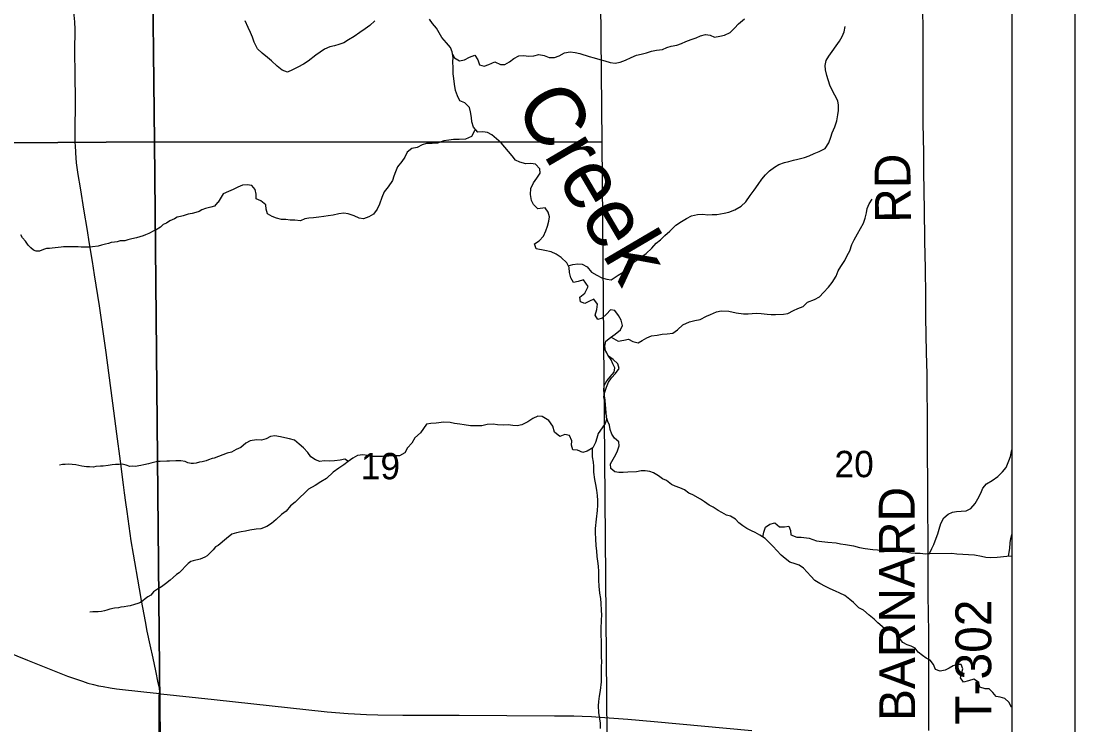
# Model space of a CAD drawing. Extents: x 0 to 34, y 0 to 22.
# Drawn here: x 23.087 to 24.758, y 10.698 to 11.815 of the extents above; entities that cross this region are included whole.
import ezdxf

# ---------------------------------------------------------------- set-up
doc = ezdxf.new("R2010")
doc.units = 0
for name, color, linetype in [('GM_X_County_Road', 7, 'Continuous'), ('GM_X_Minor_River', 7, 'Continuous'), ('GM_X_Minor_River_Text', 7, 'Continuous'), ('GM_X_Section', 7, 'Continuous'), ('GM_X_Section_Text', 7, 'Continuous'), ('GM_X_Township_Road', 7, 'Continuous'), ('GM_X_Township_Road_Text', 7, 'Continuous'), ('GM_X_US_Route', 7, 'Continuous'), ('SH_Data', 7, 'Continuous')]:
    doc.layers.add(name, color=color, linetype=linetype)

msp = doc.modelspace()

# ---------------------------------------------------------------- linework, layer by layer
at = {"layer": 'GM_X_County_Road'}
for points in [[(23.1726, 11.6218), (23.1725, 11.6372), (23.1727, 11.69), (23.1722, 11.7304), (23.1721, 11.7677), (23.1722, 11.8019), (23.1717, 11.8143), (23.1704, 11.8297), (23.1681, 11.8482), (23.1633, 11.8789), (23.1585, 11.9065), (23.1536, 11.934), (23.1493, 11.9553), (23.1329, 12.0344), (23.1224, 12.0831), (23.1147, 12.1196), (23.1137, 12.124)], [(23.3062, 10.7482), (23.3065, 10.7526), (23.3062, 10.7553), (23.3061, 10.7566), (23.3042, 10.7651), (23.3004, 10.7844), (23.2959, 10.8046), (23.2912, 10.8258), (23.2868, 10.8471), (23.2839, 10.8624), (23.2778, 10.896), (23.2745, 10.9144), (23.2717, 10.9296), (23.2668, 10.9571), (23.2647, 10.9693), (23.2614, 10.9908), (23.255, 11.0369), (23.253, 11.0512), (23.2508, 11.067), (23.2492, 11.0795), (23.2443, 11.117), (23.2385, 11.1601), (23.2338, 11.1971), (23.2218, 11.2896), (23.2109, 11.3634), (23.2033, 11.4125), (23.1997, 11.434), (23.1951, 11.4616), (23.1912, 11.4861), (23.1868, 11.5137), (23.1808, 11.5505), (23.1773, 11.572), (23.1747, 11.5905), (23.1733, 11.606), (23.1727, 11.6185), (23.1726, 11.6218)], [(23.3087, 10.1096), (23.3086, 10.1172), (23.3085, 10.1512), (23.3083, 10.2038), (23.3081, 10.2441), (23.3078, 10.3093), (23.3076, 10.3744), (23.3074, 10.4208), (23.3069, 10.4645), (23.3064, 10.5577), (23.3061, 10.6228), (23.3057, 10.6663), (23.3054, 10.6973), (23.3054, 10.7344), (23.3054, 10.7399), (23.3056, 10.7424), (23.3058, 10.7444), (23.3062, 10.7482)]]:
    msp.add_lwpolyline(points, dxfattribs=at)
at = {"layer": 'GM_X_Minor_River'}
for points in [[(23.7541, 11.7894), (23.7494, 11.7966), (23.7456, 11.8041), (23.7391, 11.8113), (23.7344, 11.8185)], [(23.7709, 11.7626), (23.7741, 11.7568), (23.7818, 11.7523), (23.7897, 11.7539), (23.7977, 11.7578), (23.806, 11.7609), (23.811, 11.7537), (23.8134, 11.7457), (23.821, 11.7439), (23.8282, 11.7463), (23.8377, 11.7505), (23.8468, 11.7464), (23.8537, 11.7461), (23.8612, 11.7507), (23.868, 11.7557), (23.876, 11.7603), (23.884, 11.7604), (23.8916, 11.7597), (23.8999, 11.7601), (23.9075, 11.7621), (23.9163, 11.7607), (23.9243, 11.7573), (23.9327, 11.7574), (23.9399, 11.7601), (23.9486, 11.7647), (23.9573, 11.7663), (23.9653, 11.7656), (23.9725, 11.7638), (23.9874, 11.759), (23.9954, 11.7567), (24.0046, 11.7545), (24.0126, 11.7523), (24.0209, 11.7497), (24.0289, 11.7487), (24.0369, 11.7502), (24.0453, 11.7534), (24.054, 11.7576), (24.0627, 11.7611), (24.0699, 11.7627), (24.0786, 11.765), (24.0866, 11.7674), (24.0942, 11.769), (24.1037, 11.7702), (24.1105, 11.7733), (24.1177, 11.7752), (24.1268, 11.7768), (24.134, 11.7796), (24.1408, 11.783), (24.1495, 11.7861), (24.1571, 11.7885), (24.1643, 11.7916), (24.1719, 11.7939), (24.1795, 11.7929), (24.1864, 11.7899), (24.1947, 11.7911), (24.202, 11.7927), (24.211, 11.7973), (24.2178, 11.8038), (24.2246, 11.8111), (24.2337, 11.8188)], [(23.6478, 11.8159), (23.6398, 11.8082), (23.6323, 11.8028), (23.624, 11.7971), (23.6149, 11.7909), (23.6058, 11.7855), (23.5986, 11.7809), (23.5907, 11.7782), (23.5838, 11.7762), (23.5763, 11.7742), (23.5679, 11.7707), (23.5611, 11.7661), (23.5539, 11.7611), (23.5418, 11.7519), (23.5343, 11.7469), (23.5256, 11.7423), (23.5173, 11.738), (23.5093, 11.7341), (23.5009, 11.7375), (23.4929, 11.7439), (23.484, 11.7522), (23.4772, 11.7574), (23.4691, 11.7642), (23.4618, 11.7714), (23.4564, 11.782), (23.4537, 11.7896), (23.4506, 11.7972), (23.4467, 11.8051), (23.4421, 11.8157)], [(23.9545, 11.4271), (23.9617, 11.4291), (23.9697, 11.4303), (23.9765, 11.4296), (23.9845, 11.4251), (23.9915, 11.4171), (23.9995, 11.4119), (24.0079, 11.4081), (24.0155, 11.4056), (24.0227, 11.4045), (24.0337, 11.4122), (24.0413, 11.4168), (24.0492, 11.4237), (24.0582, 11.4329), (24.0658, 11.4379), (24.0779, 11.4467), (24.0869, 11.4552), (24.0937, 11.4629), (24.1005, 11.4682), (24.1077, 11.4748), (24.1156, 11.482), (24.125, 11.4912), (24.1341, 11.497), (24.1417, 11.502), (24.15, 11.5063), (24.1591, 11.5083), (24.1679, 11.5087), (24.1755, 11.508), (24.1827, 11.5081), (24.1899, 11.5085), (24.2017, 11.5105), (24.2093, 11.5121), (24.2188, 11.5156), (24.2286, 11.5218), (24.2361, 11.5283), (24.2429, 11.5386), (24.2493, 11.547), (24.2557, 11.5558), (24.2613, 11.5642), (24.267, 11.5711), (24.2737, 11.5776), (24.2817, 11.5834), (24.2885, 11.5876), (24.2972, 11.5911), (24.3044, 11.5923), (24.3116, 11.5947), (24.3184, 11.5963), (24.3291, 11.599), (24.3363, 11.6017), (24.3442, 11.6052), (24.3522, 11.6083), (24.3617, 11.6133), (24.3677, 11.6221), (24.371, 11.6309), (24.3728, 11.6378), (24.3769, 11.6473), (24.3803, 11.6568), (24.3821, 11.6667), (24.3832, 11.6736), (24.3831, 11.6816), (24.3819, 11.6888), (24.3773, 11.6975), (24.3696, 11.7119), (24.3668, 11.7218), (24.3645, 11.729), (24.3625, 11.7377), (24.3617, 11.7449), (24.3635, 11.7525), (24.3676, 11.7594), (24.3729, 11.7671), (24.3793, 11.7759), (24.3845, 11.7835), (24.3887, 11.7908), (24.392, 11.7984), (24.3935, 11.8064)], [(24.0155, 11.188), (24.0135, 11.1949), (24.0127, 11.2025), (24.0122, 11.2105), (24.0106, 11.2188), (24.0125, 11.2264), (24.0151, 11.2344), (24.018, 11.2424), (24.0229, 11.2493), (24.0293, 11.2562), (24.035, 11.2639), (24.033, 11.2715), (24.0257, 11.2782), (24.0184, 11.2835), (24.0134, 11.2922), (24.0126, 11.2994), (24.0141, 11.3074), (24.0212, 11.3132), (24.0288, 11.3186), (24.0371, 11.3251), (24.0405, 11.332), (24.0381, 11.3407), (24.0342, 11.3483), (24.0285, 11.3558), (24.0216, 11.3573), (24.0148, 11.35), (24.008, 11.3439), (24.0012, 11.3415), (23.997, 11.3487), (23.9996, 11.3575), (24.0006, 11.3659), (23.9949, 11.3738), (23.988, 11.3707), (23.9805, 11.3672), (23.9736, 11.3698), (23.9728, 11.3771), (23.9807, 11.3836), (23.9859, 11.3943), (23.9786, 11.4049), (23.9703, 11.4021), (23.9627, 11.4002), (23.9585, 11.4077), (23.9561, 11.4161), (23.956, 11.4241), (23.9522, 11.4316), (23.943, 11.4399), (23.9353, 11.4452), (23.9273, 11.4489), (23.9174, 11.4515), (23.9037, 11.4537), (23.9006, 11.462), (23.9085, 11.4667), (23.9149, 11.4739), (23.919, 11.4827), (23.9213, 11.4896), (23.9235, 11.4976), (23.9246, 11.5048), (23.9226, 11.512), (23.9176, 11.5188), (23.9062, 11.5176), (23.8993, 11.524), (23.8962, 11.5308), (23.8946, 11.5403), (23.8953, 11.5498), (23.8994, 11.5586), (23.9043, 11.5662), (23.9099, 11.5739), (23.9095, 11.5807), (23.9022, 11.5883), (23.8953, 11.5894), (23.8873, 11.5885), (23.8778, 11.5915), (23.8706, 11.5945), (23.8652, 11.6013), (23.8594, 11.6081), (23.854, 11.6153), (23.8479, 11.6221), (23.8406, 11.6285), (23.833, 11.6345), (23.8261, 11.6386), (23.8188, 11.6393), (23.8112, 11.6389), (23.8043, 11.6468), (23.8016, 11.6552), (23.8008, 11.6624), (23.7996, 11.6711), (23.7976, 11.6783), (23.7903, 11.6855), (23.7823, 11.6885), (23.7788, 11.6968), (23.7757, 11.7051), (23.7741, 11.7154), (23.7729, 11.7241), (23.7717, 11.7317), (23.772, 11.7412), (23.7715, 11.7504), (23.7718, 11.7576), (23.7702, 11.7663), (23.7675, 11.7731), (23.7614, 11.7807), (23.7541, 11.7894)], [(23.8077, 11.643), (23.8055, 11.6411), (23.801, 11.6323), (23.7912, 11.6277), (23.7813, 11.6272), (23.7722, 11.6272), (23.765, 11.6263), (23.757, 11.6251), (23.7471, 11.6216), (23.7388, 11.6208), (23.7297, 11.6211), (23.7228, 11.6188), (23.7149, 11.6149), (23.7061, 11.6129), (23.699, 11.6072), (23.6952, 11.5991), (23.6904, 11.5923), (23.6836, 11.5838), (23.6806, 11.5762), (23.6776, 11.5693), (23.6754, 11.5625), (23.669, 11.5525), (23.6626, 11.5441), (23.6585, 11.5353), (23.6548, 11.525), (23.6511, 11.5166), (23.6454, 11.509), (23.6382, 11.5048), (23.6295, 11.5016), (23.6227, 11.5027), (23.6147, 11.5065), (23.6051, 11.5094), (23.5983, 11.5105), (23.5903, 11.5093), (23.5816, 11.5073), (23.5736, 11.5065), (23.5668, 11.5053), (23.5588, 11.5041), (23.5504, 11.5029), (23.5432, 11.5025), (23.5364, 11.5016), (23.5296, 11.4985), (23.5208, 11.4992), (23.5132, 11.4995), (23.5063, 11.5003), (23.4995, 11.5006), (23.4919, 11.5024), (23.4846, 11.505), (23.4774, 11.5095), (23.4754, 11.5167), (23.4746, 11.5239), (23.4669, 11.53), (23.4597, 11.5333), (23.4592, 11.5406), (23.458, 11.5478), (23.4527, 11.5546), (23.445, 11.5556), (23.4378, 11.5548), (23.4306, 11.5517), (23.423, 11.5479), (23.4155, 11.5451), (23.4071, 11.5409), (23.3991, 11.5281)], [(24.0223, 11.3139), (24.0338, 11.3072), (24.0426, 11.3092), (24.0498, 11.3104), (24.057, 11.3066), (24.065, 11.3048), (24.0718, 11.3087), (24.079, 11.3129), (24.0862, 11.3156), (24.0953, 11.3168), (24.1033, 11.3184), (24.1113, 11.3189), (24.12, 11.3201), (24.1276, 11.3255), (24.1359, 11.3331), (24.1469, 11.3378), (24.1552, 11.3401), (24.1636, 11.3417), (24.1734, 11.3468), (24.1802, 11.3495), (24.1893, 11.3541), (24.1969, 11.3557), (24.2091, 11.355), (24.2205, 11.3525), (24.2323, 11.3507), (24.2395, 11.3507), (24.2525, 11.3516), (24.2601, 11.3513), (24.2696, 11.3502), (24.2764, 11.3499), (24.2833, 11.3496), (24.2958, 11.3504), (24.3027, 11.3512), (24.3114, 11.3563), (24.3186, 11.3594), (24.3269, 11.3625), (24.3337, 11.369), (24.3451, 11.3736), (24.353, 11.3775), (24.359, 11.3844), (24.3669, 11.3928), (24.373, 11.4005), (24.3793, 11.4104), (24.3823, 11.4188), (24.3868, 11.4261), (24.3932, 11.4353), (24.3966, 11.4433), (24.401, 11.4509), (24.404, 11.4608), (24.4077, 11.4681), (24.413, 11.4776), (24.4179, 11.4864), (24.4224, 11.4944), (24.4253, 11.5024), (24.4272, 11.5108), (24.4282, 11.5181), (24.4316, 11.5253), (24.4365, 11.5326)], [(23.3991, 11.5281), (23.3983, 11.5273), (23.3935, 11.5215), (23.3874, 11.5199), (23.3791, 11.5179), (23.3734, 11.5156), (23.3689, 11.5129), (23.3635, 11.5116), (23.3579, 11.51), (23.3514, 11.5088), (23.3438, 11.5064), (23.3393, 11.5052), (23.334, 11.504), (23.3298, 11.5013), (23.3226, 11.4982), (23.317, 11.4947), (23.3117, 11.4927), (23.3079, 11.4885), (23.3008, 11.4842), (23.297, 11.4826), (23.2891, 11.478), (23.2841, 11.476), (23.2804, 11.4744), (23.2698, 11.4713), (23.2622, 11.47), (23.2561, 11.468), (23.2512, 11.4668), (23.2436, 11.4664), (23.239, 11.4652), (23.2349, 11.4643), (23.2295, 11.4639), (23.225, 11.4623), (23.2204, 11.4611), (23.2144, 11.4599), (23.2091, 11.4583), (23.2, 11.457), (23.1962, 11.4566), (23.1817, 11.4564), (23.1771, 11.4571), (23.1539, 11.4568), (23.1501, 11.4564), (23.1407, 11.4555), (23.1361, 11.4551), (23.1315, 11.4542), (23.127, 11.4542), (23.122, 11.453), (23.116, 11.4502), (23.1107, 11.4502), (23.1065, 11.4516), (23.1022, 11.4554), (23.0976, 11.4599), (23.0937, 11.4663), (23.0887, 11.4711), (23.0864, 11.476)], [(24.4559, 10.8514), (24.4456, 10.8607), (24.4395, 10.8664), (24.4314, 10.8724), (24.4226, 10.8807), (24.4154, 10.8844), (24.4069, 10.8927), (24.4008, 10.8976), (24.3932, 10.904), (24.3851, 10.9078), (24.3783, 10.9108), (24.3699, 10.9145), (24.3626, 10.9182), (24.3534, 10.9227), (24.3454, 10.9276), (24.3389, 10.9344), (24.3274, 10.9472), (24.3205, 10.9521), (24.314, 10.954), (24.306, 10.9566), (24.2984, 10.9626), (24.2922, 10.9679), (24.2853, 10.9754), (24.2796, 10.9814), (24.2727, 10.9886), (24.2665, 10.9943), (24.2581, 10.9995), (24.2509, 11.0036), (24.2448, 11.0063), (24.2375, 11.01), (24.231, 11.0145), (24.2249, 11.019), (24.2195, 11.0251), (24.2119, 11.0296), (24.2054, 11.0314), (24.1981, 11.0355), (24.192, 11.0389), (24.1844, 11.0442), (24.1779, 11.0472), (24.1702, 11.0524), (24.1641, 11.0565), (24.1519, 11.0633), (24.1458, 11.0663), (24.1385, 11.0715), (24.1312, 11.0749), (24.124, 11.0771), (24.1179, 11.0801), (24.1102, 11.0865), (24.1041, 11.0891), (24.0976, 11.0936), (24.0896, 11.0985), (24.0835, 11.1004), (24.0763, 11.1018), (24.0698, 11.1018), (24.0626, 11.1002), (24.0489, 11.0993), (24.0417, 11.0989), (24.0348, 11.0988), (24.0284, 11.1003), (24.0219, 11.1056), (24.0214, 11.1128), (24.0255, 11.1201), (24.03, 11.1273), (24.0327, 11.1334), (24.0352, 11.1411), (24.0344, 11.1475), (24.0275, 11.1535), (24.0233, 11.16), (24.0206, 11.1672), (24.0198, 11.174), (24.017, 11.1801), (24.0151, 11.1861), (24.0143, 11.1941), (24.0134, 11.2063), (24.013, 11.2139), (24.0121, 11.2207), (24.0109, 11.2295), (24.0112, 11.2371), (24.0157, 11.2447), (24.021, 11.2508), (24.027, 11.2581), (24.0281, 11.265), (24.025, 11.2714), (24.0227, 11.2775), (24.0177, 11.2846), (24.0142, 11.2915), (24.0107, 11.2975), (24.0108, 11.2996)], [(24.0156, 11.1847), (24.0129, 11.177), (24.008, 11.1701), (24.0016, 11.1609), (23.9998, 11.1537), (23.9976, 11.1464), (23.9934, 11.1384), (23.9844, 11.1326), (23.9775, 11.1307), (23.9688, 11.1344), (23.9615, 11.1347), (23.9596, 11.1423), (23.9599, 11.1492), (23.9564, 11.1579), (23.9488, 11.1594), (23.9412, 11.1563), (23.9328, 11.163), (23.9297, 11.1725), (23.9235, 11.1816), (23.9132, 11.188), (23.9059, 11.1883), (23.8984, 11.1848), (23.8901, 11.1794), (23.881, 11.1744), (23.8734, 11.1728), (23.8665, 11.1735), (23.8589, 11.1746), (23.8513, 11.1742), (23.8422, 11.1748), (23.8353, 11.1755), (23.8258, 11.1751), (23.8175, 11.1731), (23.8068, 11.173), (23.7996, 11.1733), (23.7893, 11.1744), (23.7825, 11.1755), (23.7741, 11.1769), (23.7669, 11.1784), (23.757, 11.1787), (23.7448, 11.1771), (23.7365, 11.177), (23.7296, 11.1758), (23.7247, 11.1689), (23.7199, 11.1617), (23.7112, 11.154), (23.7063, 11.1456), (23.6995, 11.1379), (23.695, 11.1303), (23.6867, 11.1257), (23.6783, 11.1256), (23.67, 11.1251), (23.6597, 11.1243), (23.6521, 11.1242), (23.6441, 11.1245), (23.6358, 11.126), (23.6285, 11.1271), (23.6202, 11.1259), (23.613, 11.122), (23.6054, 11.1162), (23.5986, 11.1109), (23.5903, 11.1058), (23.5816, 11.0993), (23.571, 11.0897), (23.562, 11.0843), (23.5529, 11.0785), (23.5427, 11.0724), (23.5359, 11.0662), (23.5287, 11.0593), (23.5212, 11.0517), (23.514, 11.0459), (23.5069, 11.0379), (23.4997, 11.0325), (23.491, 11.0244), (23.4838, 11.0179), (23.4763, 11.0133), (23.4668, 11.0094), (23.4592, 11.0089), (23.4493, 11.0073), (23.4425, 11.0061), (23.4357, 11.0046), (23.4284, 11.0034), (23.4209, 11.0014), (23.4122, 10.9945)], [(23.6057, 11.1165), (23.6001, 11.12), (23.5925, 11.1188), (23.5837, 11.1176), (23.5758, 11.1171), (23.5674, 11.1174), (23.5606, 11.1166), (23.5533, 11.1189), (23.546, 11.1237), (23.5414, 11.1309), (23.5345, 11.1381), (23.5276, 11.1441), (23.52, 11.1501), (23.5123, 11.1524), (23.5051, 11.1538), (23.4979, 11.1557), (23.4891, 11.1571), (23.4823, 11.1559), (23.4751, 11.1524), (23.4679, 11.1501), (23.4599, 11.1508), (23.45, 11.1492), (23.4428, 11.1453), (23.4349, 11.1388), (23.4277, 11.1353), (23.4205, 11.1315), (23.4137, 11.1295), (23.3931, 11.122)], [(23.9922, 11.1376), (23.9924, 11.124), (23.994, 11.1156), (23.9945, 11.1088), (23.9945, 11.0997), (23.9958, 11.0879), (23.9974, 11.0799), (23.9993, 11.0712), (24.0002, 11.0624), (24.0006, 11.0548), (24.0007, 11.0472), (24.0004, 11.0385), (23.9986, 11.0248), (23.9972, 11.0103), (23.9973, 11.0031), (23.9977, 10.9936), (23.9982, 10.9826), (23.999, 10.9746), (23.9995, 10.9658), (24.0007, 10.9582), (24.0019, 10.9503), (24.0023, 10.9419), (24.0025, 10.9282), (24.0029, 10.9187), (24.0042, 10.9073), (24.0054, 10.899), (24.0058, 10.8914), (24.0067, 10.8807), (24.0071, 10.8727), (24.0068, 10.8651), (24.0062, 10.8503), (24.0059, 10.8404), (24.0067, 10.832), (24.0068, 10.8214), (24.0065, 10.8138), (24.0065, 10.8062), (24.007, 10.799), (24.0067, 10.7906), (24.0064, 10.783), (24.0065, 10.7666), (24.0051, 10.7533), (24.0033, 10.7442), (24.0026, 10.7358), (24.0019, 10.7286), (24.0023, 10.7183), (24.0039, 10.7081), (24.0048, 10.7012), (24.0052, 10.6929)], [(24.5271, 10.9705), (24.5309, 10.9782), (24.5339, 10.985), (24.5376, 10.9946), (24.5406, 11.0018), (24.5424, 11.0091), (24.5454, 11.0182), (24.5499, 11.027), (24.5567, 11.0328), (24.5635, 11.0362), (24.5703, 11.0371), (24.5776, 11.0375), (24.5855, 11.0383), (24.5927, 11.0418), (24.5999, 11.0498), (24.604, 11.0571), (24.6089, 11.0663), (24.6119, 11.0739), (24.6175, 11.0812), (24.6266, 11.0862), (24.6357, 11.0927), (24.6428, 11.1), (24.6488, 11.1069), (24.6529, 11.1176), (24.6555, 11.1245), (24.6574, 11.1325), (24.6579, 11.1349)], [(23.3931, 11.122), (23.3899, 11.1211), (23.3838, 11.1191), (23.3801, 11.1176), (23.3736, 11.116), (23.3698, 11.1152), (23.3641, 11.1136), (23.36, 11.1131), (23.3562, 11.1135), (23.3512, 11.1145), (23.347, 11.1164), (23.3401, 11.1174), (23.3318, 11.1177), (23.3219, 11.1172), (23.3177, 11.1171), (23.3071, 11.1166), (23.3029, 11.1162), (23.2926, 11.1137), (23.2889, 11.1129), (23.2813, 11.1109), (23.2763, 11.1101), (23.2676, 11.1085), (23.2627, 11.1088), (23.2589, 11.1087), (23.2531, 11.1106), (23.247, 11.112), (23.2421, 11.1119), (23.2364, 11.1119), (23.2311, 11.1114), (23.2246, 11.1102), (23.2166, 11.1093), (23.2128, 11.1089), (23.2052, 11.1084), (23.2014, 11.1076), (23.195, 11.1079), (23.1904, 11.1078), (23.1828, 11.1089), (23.1736, 11.111), (23.1679, 11.1117), (23.1626, 11.112), (23.1565, 11.1119), (23.1523, 11.1119), (23.1474, 11.1107)], [(24.2632, 10.9963), (24.2645, 11.0041), (24.2671, 11.0121), (24.2743, 11.0171), (24.2819, 11.0191), (24.2892, 11.0127), (24.2972, 11.0128), (24.304, 11.014), (24.3071, 11.0068), (24.3072, 10.9999), (24.3171, 10.9962), (24.3239, 10.9963), (24.3365, 10.9948), (24.3483, 10.9907), (24.3567, 10.9893), (24.3662, 10.9882), (24.3791, 10.9872), (24.3864, 10.9857), (24.394, 10.985), (24.4069, 10.9829), (24.4165, 10.9799), (24.4252, 10.9784), (24.4374, 10.977), (24.4446, 10.9763), (24.4572, 10.9757), (24.4667, 10.975), (24.4781, 10.9743), (24.4899, 10.9729), (24.4979, 10.9714), (24.5047, 10.9711), (24.5127, 10.9708), (24.5211, 10.9701), (24.5279, 10.9705), (24.5625, 10.9708), (24.5705, 10.9698), (24.58, 10.9694), (24.5892, 10.9691), (24.5987, 10.9681), (24.6097, 10.9663), (24.6166, 10.9648), (24.6246, 10.9641), (24.6348, 10.9646), (24.6497, 10.9662), (24.6579, 10.9667)], [(24.6527, 10.9664), (24.6545, 10.9784), (24.6552, 10.9872), (24.6563, 10.9944), (24.6579, 11.0005)], [(23.4122, 10.9945), (23.3993, 10.9834), (23.3951, 10.981), (23.3914, 10.9764), (23.3865, 10.9718), (23.382, 10.9668), (23.3779, 10.9645), (23.3707, 10.9613), (23.3597, 10.9589), (23.3559, 10.9577), (23.3518, 10.9546), (23.3375, 10.94), (23.3333, 10.9373), (23.3277, 10.9323), (23.3228, 10.9284), (23.3157, 10.9226), (23.3093, 10.9176), (23.3032, 10.9141), (23.2968, 10.9094), (23.2923, 10.9044), (23.2878, 10.9017), (23.2836, 10.8986), (23.2799, 10.8955), (23.2761, 10.8928), (23.2719, 10.8913), (23.2663, 10.8897), (23.2594, 10.8873), (23.2557, 10.8869), (23.25, 10.8856), (23.245, 10.8852), (23.2409, 10.8844), (23.2348, 10.8835), (23.2272, 10.8819), (23.2226, 10.8807), (23.2189, 10.8795), (23.2139, 10.8783), (23.209, 10.8779), (23.2002, 10.8778), (23.1957, 10.8773)], [(24.6153, 10.7557), (24.6069, 10.7582), (24.605, 10.7662), (24.5977, 10.7711), (24.589, 10.7687), (24.581, 10.7664), (24.5764, 10.7732), (24.5782, 10.7793), (24.5804, 10.7877), (24.5773, 10.7945), (24.5713, 10.7945), (24.5648, 10.7921), (24.5584, 10.7883), (24.5523, 10.7852), (24.544, 10.7836), (24.5367, 10.7862), (24.5336, 10.7945), (24.5286, 10.801), (24.5221, 10.8043), (24.516, 10.8085), (24.5095, 10.8137), (24.5045, 10.8201), (24.4984, 10.8235), (24.4919, 10.8258), (24.485, 10.8295), (24.4797, 10.8363), (24.475, 10.8431), (24.4682, 10.8476), (24.4617, 10.8498), (24.4559, 10.8514)], [(24.6579, 10.7259), (24.6574, 10.7267), (24.6531, 10.7347), (24.6466, 10.7403), (24.6394, 10.7425), (24.6329, 10.7436), (24.6279, 10.7497), (24.6218, 10.7557), (24.6153, 10.7557)]]:
    msp.add_lwpolyline(points, dxfattribs=at)
at = {"layer": 'GM_X_Section'}
for points in [[(23.2871, 12.632), (23.2872, 12.6207), (23.2983, 11.6235), (22.3015, 11.617), (22.2979, 12.6206)], [(23.2872, 12.6207), (23.9982, 12.6247), (24.0077, 11.623), (23.2983, 11.6235)], [(23.2983, 11.6235), (23.3079, 10.6196), (22.3097, 10.6062), (22.3015, 11.617)], [(23.2983, 11.6235), (24.0077, 11.623), (24.0161, 10.618), (23.3079, 10.6196)]]:
    msp.add_lwpolyline(points, close=True, dxfattribs=at)
at = {"layer": 'GM_X_Township_Road'}
msp.add_lwpolyline([(24.5263, 10.6899), (24.5264, 10.7489), (24.5264, 10.7986), (24.5263, 10.8452), (24.5254, 10.9042), (24.5252, 10.9353), (24.5254, 10.9697), (24.5252, 10.9877), (24.5246, 11.0471), (24.524, 11.1651), (24.5234, 11.2552), (24.5226, 11.2894), (24.5217, 11.3452), (24.5214, 11.3794), (24.5208, 11.4229), (24.5197, 11.4663), (24.5197, 11.485), (24.5194, 11.4992), (24.5191, 11.5229), (24.5189, 11.5378), (24.5187, 11.5501), (24.5184, 11.5718), (24.5182, 11.5935), (24.5181, 11.609), (24.5179, 11.6276), (24.5174, 11.6555), (24.5174, 11.6679), (24.5174, 11.6875), (24.5175, 11.705), (24.5173, 11.7175), (24.5173, 11.7235), (24.5173, 11.7378), (24.5173, 11.7447), (24.5173, 11.7699), (24.5171, 11.7945), (24.517, 11.8093), (24.5169, 11.826)], dxfattribs=at)
at = {"layer": 'GM_X_US_Route'}
for points in [[(22.6302, 11.0143), (22.6499, 11.0041), (22.7111, 10.9737), (22.767, 10.9465), (22.8425, 10.9097), (22.8873, 10.8883), (22.9077, 10.879), (22.9156, 10.8754), (22.9356, 10.8667), (22.9617, 10.8557), (22.9873, 10.8454), (23.0142, 10.8346), (23.0969, 10.8014), (23.1605, 10.7761), (23.1839, 10.7677), (23.1926, 10.7649), (23.2017, 10.7625), (23.2095, 10.7607), (23.2167, 10.7592), (23.2277, 10.7573), (23.2382, 10.7558), (23.2814, 10.751), (23.3062, 10.7482), (23.3082, 10.748)], [(23.3082, 10.748), (23.3927, 10.7389), (23.5719, 10.7194), (23.6056, 10.7168), (23.6153, 10.7161), (23.6345, 10.7151), (23.6525, 10.7147), (23.6919, 10.7142), (23.7278, 10.7141), (23.7816, 10.7138), (23.9324, 10.7131), (23.9631, 10.7127), (23.9762, 10.7123), (23.9911, 10.7118), (24.0194, 10.71), (24.0491, 10.7076), (24.0907, 10.704), (24.2455, 10.6898)]]:
    msp.add_lwpolyline(points, dxfattribs=at)
at = {"layer": 'SH_Data'}
for p, q in [((24.7579, 16.0775), (24.7579, 9.0775)), ((24.6579, 15.9775), (24.6579, 9.1775))]:
    msp.add_line(p, q, dxfattribs=at)

# ---------------------------------------------------------------- texts
at = {"layer": 'GM_X_Minor_River_Text'}
msp.add_text('Creek', height=0.09472, rotation=300.4676, dxfattribs=at).set_placement((23.8681, 11.6818))
at = {"layer": 'GM_X_Section_Text'}
for s, p in [('20', (24.3766, 11.0915)), ('19', (23.6254, 11.0882))]:
    msp.add_text(s, height=0.04186, rotation=0, dxfattribs=at).set_placement(p)
at = {"layer": 'GM_X_Township_Road_Text'}
for s, rotation, p in [('RD', 90.4937, (24.4978, 11.4954)), ('BARNARD', 90.1396, (24.5045, 10.7047)), ('T-302', 90, (24.6252, 10.6989))]:
    msp.add_text(s, height=0.05682, rotation=rotation, dxfattribs=at).set_placement(p)

doc.saveas('drawing.dxf')
